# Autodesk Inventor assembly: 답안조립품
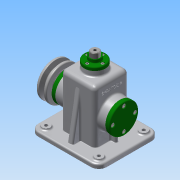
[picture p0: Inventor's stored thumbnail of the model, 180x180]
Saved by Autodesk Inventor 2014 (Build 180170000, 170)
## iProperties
Created: 2015-12
Part Number: 답안조립품
Document SubType Name: Assembly
Designer: Administrator
Author: Administrator
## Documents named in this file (19)
- D:\3D프린트손효\451225V1017\답안조립품.iam
- D:\3D프린트손효\451225V1017\1-본체.ipt
- D:\3D프린트손효\451225V1017\뒤커버.ipt
- D:\3D프린트손효\451225V1017\볼트 M4 x 10.ipt
- D:\3D프린트손효\451225V1017\베어링 15 x 35 x 11.ipt
- D:\3D프린트손효\451225V1017\앞커버.ipt
- D:\3D프린트손효\451225V1017\오일실 15 25 7.ipt
- D:\3D프린트손효\451225V1017\편심축.ipt
- D:\3D프린트손효\451225V1017\키 5 x 5 x 14.ipt
- D:\3D프린트손효\451225V1017\V-벨트풀리.ipt
- D:\3D프린트손효\451225V1017\와셔.ipt
- D:\3D프린트손효\451225V1017\볼트 M6 x 12.ipt
- D:\3D프린트손효\451225V1017\멈춤링 15 x 1.ipt
- D:\3D프린트손효\451225V1017\볼트 M3 x 8.ipt
- D:\3D프린트손효\451225V1017\상부부시.ipt
- D:\3D프린트손효\451225V1017\슬라이드바.ipt
- D:\3D프린트손효\451225V1017\고정핀.ipt
- D:\3D프린트손효\451225V1017\링크.ipt
- D:\3D프린트손효\451225V1017\멈춤링 6 x 5.ipt
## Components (16 placed, 6 different names)
1. 1-본체:1
2. V-벨트풀리:1
3. ISO 4018 M6 x 12:1
4. 고정핀:1 — 플러쉬:2
5. ISO 4762 M4 x 10:1
6. ISO 4762 M4 x 10:2
7. ISO 4762 M4 x 10:3
8. ISO 4762 M4 x 10:4
9. ISO 4762 M4 x 10:5
10. ISO 4762 M4 x 10:6
11. ISO 4762 M4 x 10:7
12. ISO 4762 M4 x 10:8
13. ISO 4762 M3 x 8:1
14. ISO 4762 M3 x 8:2
15. ISO 4762 M3 x 8:3
16. ISO 4762 M3 x 8:4
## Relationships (1: Flush 1)
- 플러쉬:2 [Flush]: 고정핀:1
